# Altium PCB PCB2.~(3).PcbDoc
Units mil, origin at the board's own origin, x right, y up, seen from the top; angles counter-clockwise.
Board outline 6000 x 4000 mil, 2 copper layers (Top Layer, Bottom Layer); 81 components, 33 nets, 200 pads, 0 vias.
Unrouted connection lines stored in the file: 161.
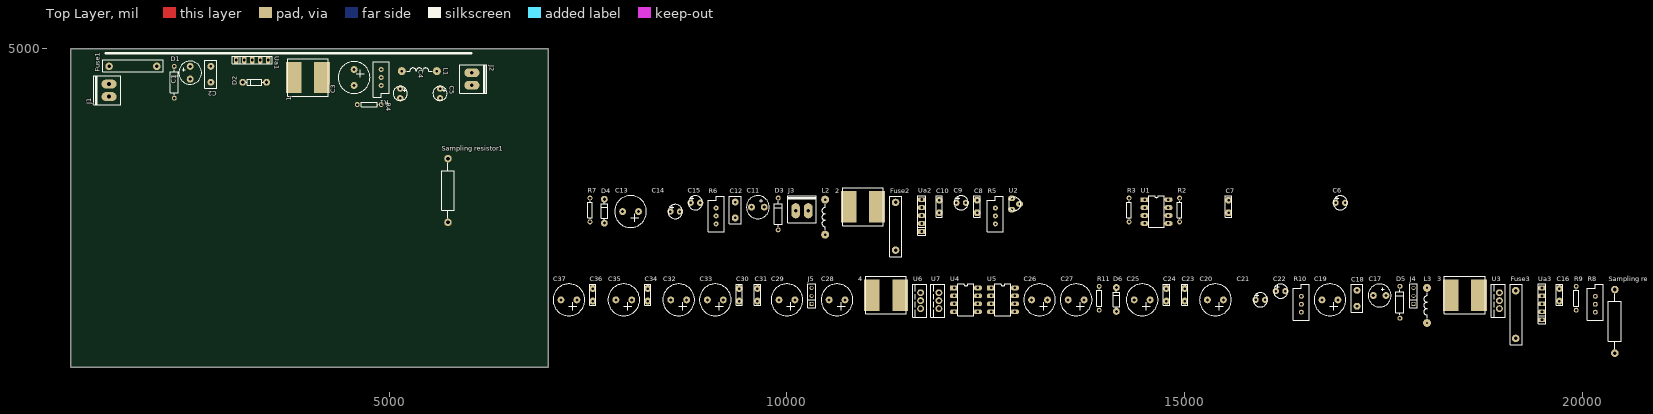
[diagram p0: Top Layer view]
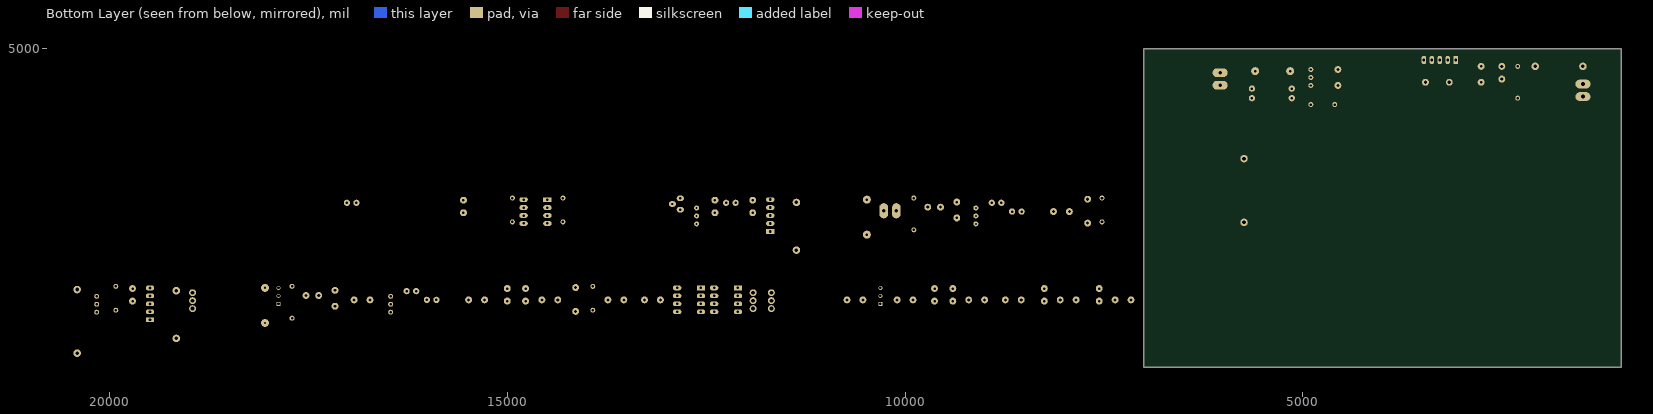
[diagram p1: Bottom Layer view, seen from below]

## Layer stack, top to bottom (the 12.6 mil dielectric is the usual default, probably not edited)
Top Layer: signal copper 1.4
Dielectric: dielectric 12.6, FR-4, Dk 4.8
Bottom Layer: signal copper 1.4

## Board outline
1000,1000 7000,1000 7000,5000 1000,5000

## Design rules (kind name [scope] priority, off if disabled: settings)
Clearance [All] p1: gap=10
PolygonConnect [All] p1: connectstyle=Relief reliefconductorwidth=10 reliefentries=4 polygonreliefangle="90 Angle"
RoutingVias [All] p1: holewidth=28 width=50 viastyle="Through Hole" minholewidth=28 minwidth=50 maxholewidth=28 maxwidth=50
SilkscreenOverComponentPads [All] p1: minsilkscreentomaskgap=10
SolderMaskExpansion [All] p1: expansion=4
TestPointUsage [All] p1: valid=0 allowmultiple=FALSE
Testpoint [All] p1: side=15 testpointundercomponent=TRUE minsize=40 maxsize=100 preferedsize=60 minholesize=0 maxholesize=40 preferedholesize=32 testpointgrid=1 style=1023 order=0-112345678
Width [All] p1: maxlimit=10 minlimit=10 preferedwidth=10
23 further rules are at their usual default settings.

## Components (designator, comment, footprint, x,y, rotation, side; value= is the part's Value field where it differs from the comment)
1 "330uh" L 4000,4640 r90 top
2 "330uh" L 10975,3015 r90 top
3 "330uh" L 18540,1905 r90 top
4 "330uh" L 11265,1905 r90 top
C1 "1000uf" RB2 2480,4780 r90 top
C2 "104" RAD0.2 2760,4780 r270 top
C3 "2000uh" RB3 4560,4740 r90 top
C4 "100uf" RB1 5140,4440 r270 top
C5 "100uf" RB1 5640,4440 r270 top
C6 "10uf" RB1 16955,3065 r0 top
C7 "104" RAD0.15 15550,2940 r90 top
C8 "104" RAD0.15 12390,2940 r90 top
C9 "10uf" RB1 12190,3065 r0 top
C10 "104" RAD0.15 11915,2940 r90 top
C11 "1000uf" RB2 9715,3030 r0 top
C12 "104" RAD0.2 9350,2875 r90 top
C13 "2000uf" RB3 8135,2955 r0 top
C14 "100uf3" RB1 8595,2955 r0 top
C15 "100" RB1 8850,3065 r0 top
C16 "104" RAD0.15 19710,1830 r90 top
C17 "1000uf" RB2 17530,1920 r0 top
C18 "104" RAD0.2 17165,1765 r90 top
C19 "10uf" RB3 16925,1845 r0 top
C20 "2000uf" RB3 15485,1845 r0 top
C21 "100uf" RB1 15950,1845 r0 top
C22 "100uf" RB1 16205,1955 r0 top
C23 "104" RAD0.15 15000,1830 r90 top
C24 "104" RAD0.15 14770,1830 r90 top
C25 "10uf" RB3 14565,1845 r0 top
C26 "100uf" RB3 13275,1845 r0 top
C27 "100uf" RB3 13735,1845 r0 top
C28 "10uf" RB3 10730,1845 r0 top
C29 "10uf" RB3 10100,1845 r0 top
C30 "104" RAD0.15 9400,1830 r90 top
C31 "104" RAD0.15 9630,1830 r90 top
C32 "10uf" RB3 8740,1845 r0 top
C33 "10uf" RB3 9200,1845 r0 top
C34 "104" RAD0.15 8250,1830 r90 top
C35 "10uf" RB3 8050,1845 r0 top
C36 "104" RAD0.15 7560,1830 r90 top
C37 "10uf" RB3 7360,1845 r0 top
D1 "IN4007" DIODE0.4 2300,4380 r90 top
D2 "MBR360" DIODE0.2 3340,4580 r180 top
D3 "IN4007" DIODE0.4 9890,2725 r90 top
D4 "MBR360" DIODE0.2 7705,2930 r90 top
D5 "IN4007" DIODE0.4 17705,1615 r90 top
D6 "MBR360" DIODE0.2 14140,1820 r90 top
Fuse1 "4A" RAD0.5 1780,4780 r180 top
Fuse2 "4A" RAD0.5 11365,2770 r90 top
Fuse3 "4A" RAD0.5 19160,1660 r90 top
J1 "CON2" BCON2 1480,4400 r90 top
J2 "CON2" BCON2 6040,4700 r270 top
J3 "CON2" BCON2 10110,2965 r0 top
J4 "CON3" sip3 17875,1795 r90 top
J5 "CON3" sip3 10310,1795 r90 top
L1 "20uh" LHF440 5160,4720 r0 top
L2 "20uh" LHF440 10480,2665 r90 top
L3 "20uh" LHF440 18045,1555 r90 top
R1 "50K" VR5 4900,4740 r270 top
R2 "1k" AXIAL0.3 14935,2825 r90 top
R3 "1k" AXIAL0.3 14300,2825 r90 top
R4 "1.21K" AXIAL0.3 4600,4300 r0 top
R5 "5k" VR5 12620,2800 r90 top
R6 "50k" VR5 9110,2800 r90 top
R7 "1k" AXIAL0.3 7525,2825 r90 top
R8 "5k" VR5 20160,1690 r90 top
R9 "1.21K" AXIAL0.3 19920,1715 r90 top
R10 "50k" VR5 16465,1690 r90 top
R11 "1.21k" AXIAL0.3 13925,1715 r90 top
"Sampling resistor1" "0.1" AXIAL0.8 5740,2820 r90 top
"Sampling resistor 1" "0.1   100w" AXIAL0.8 20405,1175 r90 top
U1 "OPA2228" DIP-8 14495,3105 r0 top
U2 "TL431" TO92B 12825,3120 r0 top
U3 "7805" TO257V 18955,1735 r90 top
U4 "ICL7662" DIP-8 12100,1995 r0 top
U5 "ICL7662" DIP-8 12565,1995 r0 top
U6 "7915" TO257V 11680,1735 r90 top
U7 "7905" TO257V 11910,1735 r90 top
Ua1 "LM2596HVADJ" SIP-5 3080,4860 r0 top
Ua2 "LM2596HVADJ" SIP-5 11695,2705 r90 top
Ua3 "LM2596HVADJ" SIP-5 19490,1595 r90 top

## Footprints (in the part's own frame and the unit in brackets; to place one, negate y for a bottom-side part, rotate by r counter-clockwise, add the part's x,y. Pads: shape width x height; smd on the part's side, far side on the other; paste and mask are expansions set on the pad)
AXIAL0.3 [mil]
  round 62 hole 32: 1(0,0) 2(300,0)
  silkscreen extent 41,-30 259,30
AXIAL0.8 [mm]
  round 2.4 hole 1.2: 1(0,0) 2(20.32,0)
  silkscreen extent 1.27,-2.03 19.05,2.03
BCON2 [mil]
  oval 110x190 hole 47.24: 1(0,0) 2(157.48,0)
  silkscreen extent -100,-150 260,190
DIODE0.2 [mm]
  round 2.2 hole 1: 1(-3.048,0) 2(4.572,0)
  silkscreen extent -2.03,-1.02 3.56,1.02
DIODE0.4 [mil]
  round 62 hole 32: 1(0,0) 2(400,0)
  silkscreen extent 40,-50 360,50
DIP-8 [mm]
  rect 2.7x1.5 hole 0.8: 1(0,0)
  oval 2.7x1.5 hole 0.8: 2(0,-2.54) 3(0,-5.08) 4(0,-7.62) 5(7.62,-7.62) 6(7.62,-5.08) 7(7.62,-2.54) 8(7.62,0)
  silkscreen extent 1.27,-8.89 6.35,1.27
L [mm]
  rect 10x5 smd: 1(0,5) 2(0,-4)
  silkscreen extent -6,-6 6,7
LHF440 [mil]
  round 100 hole 30: 1(0,0) 2(440,0)
  silkscreen extent 60,0 380,40
RAD0.2 [mm]
  round 2.2 hole 0.8: 1(0,0) 2(5.08,0)
  silkscreen extent -1.91,-1.91 6.98,1.91
RAD0.5 [mm]
  round 2.4 hole 1.1: 1(-7.62,0) 2(7.62,0)
  silkscreen extent -9.65,-2.03 9.65,1.78
RAD0.15 [mm]
  round 2.2 hole 0.8: 1(0,0) 2(4,0)
  silkscreen extent -1.4,-1 5.4,1
RB1 [mm]
  round 2 hole 0.8: 1(-1.524,0) 2(1.524,0)
  silkscreen extent -2.27,-2.27 2.27,2.27
RB2 [mm]
  round 2.2 hole 1: 1(0,-0.508) 2(-4.064,-0.508)
  silkscreen extent -5.69,-4.17 1.63,3.15
RB3 [mm]
  round 2.2 hole 1: 1(0,0) 2(-5.08,0)
  silkscreen extent -7.62,-5.08 2.54,5.08
sip3 [mil]
  rect 50x50 hole 32: 1(0,0)
  round 50 hole 32: 2(100,0) 3(200,0)
  silkscreen extent -50,-50 250,50
SIP-5 [mm]
  rect 1.5x2.7 hole 0.9: 1(0,0)
  oval 1.5x2.7 hole 0.9: 2(2.54,0) 3(5.08,0) 4(7.62,0) 5(10.16,0)
  silkscreen extent -1.27,-1.27 11.43,1.27
TO92B [mil]
  oval 90x70 hole 30: 1(0,0) 2(100,-70) 3(0,-140)
  silkscreen extent -30,-155 115,15
TO257V [mm]
  round 2.2 hole 1.2: 1(0,0) 2(2.54,0) 3(5.08,0)
  silkscreen extent -2.75,-1.91 7.83,2.54
VR5 [mil]
  round 62 hole 28: 1(0,0) 2(100,0) 3(200,0)
  silkscreen extent -100,-100 350,100

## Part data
1 2 3 4: library part INDUCTOR2
C1 C3 C4 C5 C6 C9 C11 C13 C14 C15 C17 C19 C20 C21 C22 C25 C26 C27 C28 C29 C32 C33 C35 C37: library part CAP3
C2 C7 C8 C10 C12 C16 C18 C23 C24 C30 C31 C34 C36: library part CAP1
D1 D2 D3 D4 D5 D6: library part DIODE
Fuse1 Fuse2 Fuse3: library part FUSE1, "Fuse"
J1 J2 J3 J4 J5: "Connector"
L1 L2 L3: library part INDUCTOR
R1 R5 R6 R8 R10: library part RPOT2, "Potentiometer"
R2 R3 R4 R7 R9 R11 "Sampling resistor1" "Sampling resistor 1": library part RES
U1: library part NE5532
U2: "Programmable Voltage Reference"
U3: library part 78**
U6 U7: library part 79**
Ua1 Ua2 Ua3: library part LM2596T-5.0, "Simple Switcher Power Converter 150 kHz 3A Step Down Voltage Regulator"

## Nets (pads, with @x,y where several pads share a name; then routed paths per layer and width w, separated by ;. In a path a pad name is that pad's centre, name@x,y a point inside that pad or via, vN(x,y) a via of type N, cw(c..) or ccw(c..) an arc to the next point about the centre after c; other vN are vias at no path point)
"5V 3A": C5.1 J2.1 L1.2
"8V 3A": C15.1 J3.1 L2.2
+5V: C6.1 C7.1 C24.1 C25.1 J5.1 R2.2 U1.8 U3.3
+15V: C19.1 C22.1 C23.1 J4.1 L3.2 U3.1
-5V: C9.2 C10.2 C31.1 C33.2 J5.3 U1.4 U7.3
-15V: C34.1 C35.2 J4.3 U6.3 U7.2
FB5V: U1.1 Ua1.5
FB8V: U1.7 Ua2.5
GND: "Sampling resistor1.2" "Sampling resistor 1.2" C1.2 C2.2 C3.2 C4.2 C5.2 C6.2 C7.2 C8.2 C9.1 C10.1 C11.2 C12.2 C13.2 C14.2 C15.2 C16.2 C17.2 C18.2 C19.2 C20.2 C21.2 C22.2 C23.2 C24.2 C25.2 C26.2 C27.2 C30.2 C31.2 C32.1 C33.1 C34.2 C35.1 C36.2 C37.1 D1.1 D2.1 D3.1 D4.1 D5.1 D6.1 J1.1 J4.2 J5.2 R4.1 R5.2 R5.3 R8.2 R8.3 R9.1 R11.1 U2.2 U3.2 U4.3 U5.3 U6.1 U7.1 Ua1.3 Ua2.3 Ua3.3 Ua3.5
Net1_1: 1.1 D2.2 Ua1.2
Net1_2: 1.2 C3.1 C4.1 L1.1 R1.1
Net2_1: 2.1 D4.2 Ua2.2
Net2_2: 2.2 C13.1 C14.1 L2.1 R6.1
Net3_1: 3.1 D6.2 Ua3.2
Net3_2: 3.2 C20.1 C21.1 L3.1 R10.1
Net4_1: 4.1 C36.1 C37.2 U4.5 U5.5
Net4_2: 4.2 C30.1 C32.2 U6.2
NetC1_1: C1.1 C2.1 D1.2 Fuse1.1 Ua1.1
NetC8_1: C8.1 C16.1 R2.1 R3.1 R7.1 U2.1 U2.3
NetC11_1: C11.1 C12.1 D3.2 Fuse2.1 Ua2.1
NetC17_1: C17.1 C18.1 D5.2 Fuse3.1 Ua3.1
NetC26_1: C26.1 C27.1 Fuse1.2 Fuse2.2 Fuse3.2 J1.2 U4.8 U5.8
NetC28_1: C28.1 U4.2
NetC28_2: C28.2 U4.4
NetC29_1: C29.1 U5.2
NetC29_2: C29.2 U5.4
NetJ2_2: "Sampling resistor1.1" J2.2 U1.3
NetJ3_2: "Sampling resistor 1.1" J3.2 U1.5
NetR1_2: R1.2 R1.3 R4.2 Ua1.4
NetR3_2: R3.2 R5.1 U1.2
NetR6_2: R6.2 R6.3 R9.2 Ua2.4
NetR7_2: R7.2 R8.1 U1.6
NetR10_2: R10.2 R10.3 R11.2 Ua3.4
pads on no net: U4.1 U4.6 U4.7 U5.1 U5.6 U5.7

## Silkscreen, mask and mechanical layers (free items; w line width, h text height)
Top Overlay:
  lines w30: 1435,4945 6035,4945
